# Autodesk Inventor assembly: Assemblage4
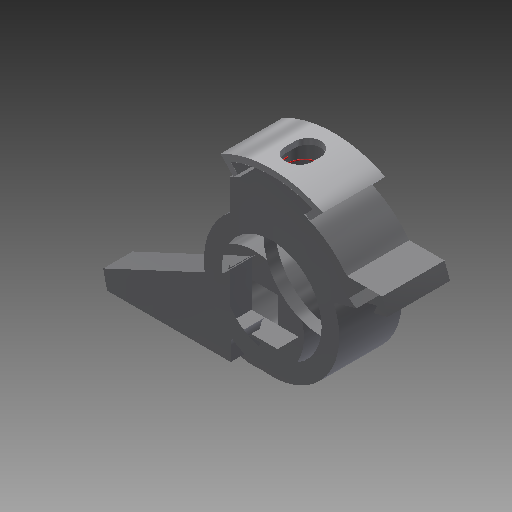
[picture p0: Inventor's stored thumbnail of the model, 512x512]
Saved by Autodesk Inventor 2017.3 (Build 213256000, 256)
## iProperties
Created: 2007-11
Part Number: Assemblage4
Material: Générique
Document SubType Name: Assembly
Designer: ficho
Author: ficho
Sending System: SolidWorks 2009
Last Author: christophe
Last Saved: 2011-02-10
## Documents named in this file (4)
- G:\travail\année 2019-2020\réforme\toussaint\Serrure biométrique SET\Documentations_pedagogique\Modelisation_Solidworks\Assemblage4.iam
- G:\travail\année 2019-2020\réforme\toussaint\Serrure biométrique SET\Documentations_pedagogique\Modelisation_Solidworks\Pièce14.ipt
- G:\travail\année 2019-2020\réforme\toussaint\Serrure biométrique SET\Documentations_pedagogique\Modelisation_Solidworks\ressort1.ipt
- G:\travail\année 2019-2020\réforme\toussaint\Serrure biométrique SET\Documentations_pedagogique\Modelisation_Solidworks\Pièce15.ipt
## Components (3 placed, 3 different names)
1. Pièce14:1
2. ressort1:1
3. Pièce15:1
